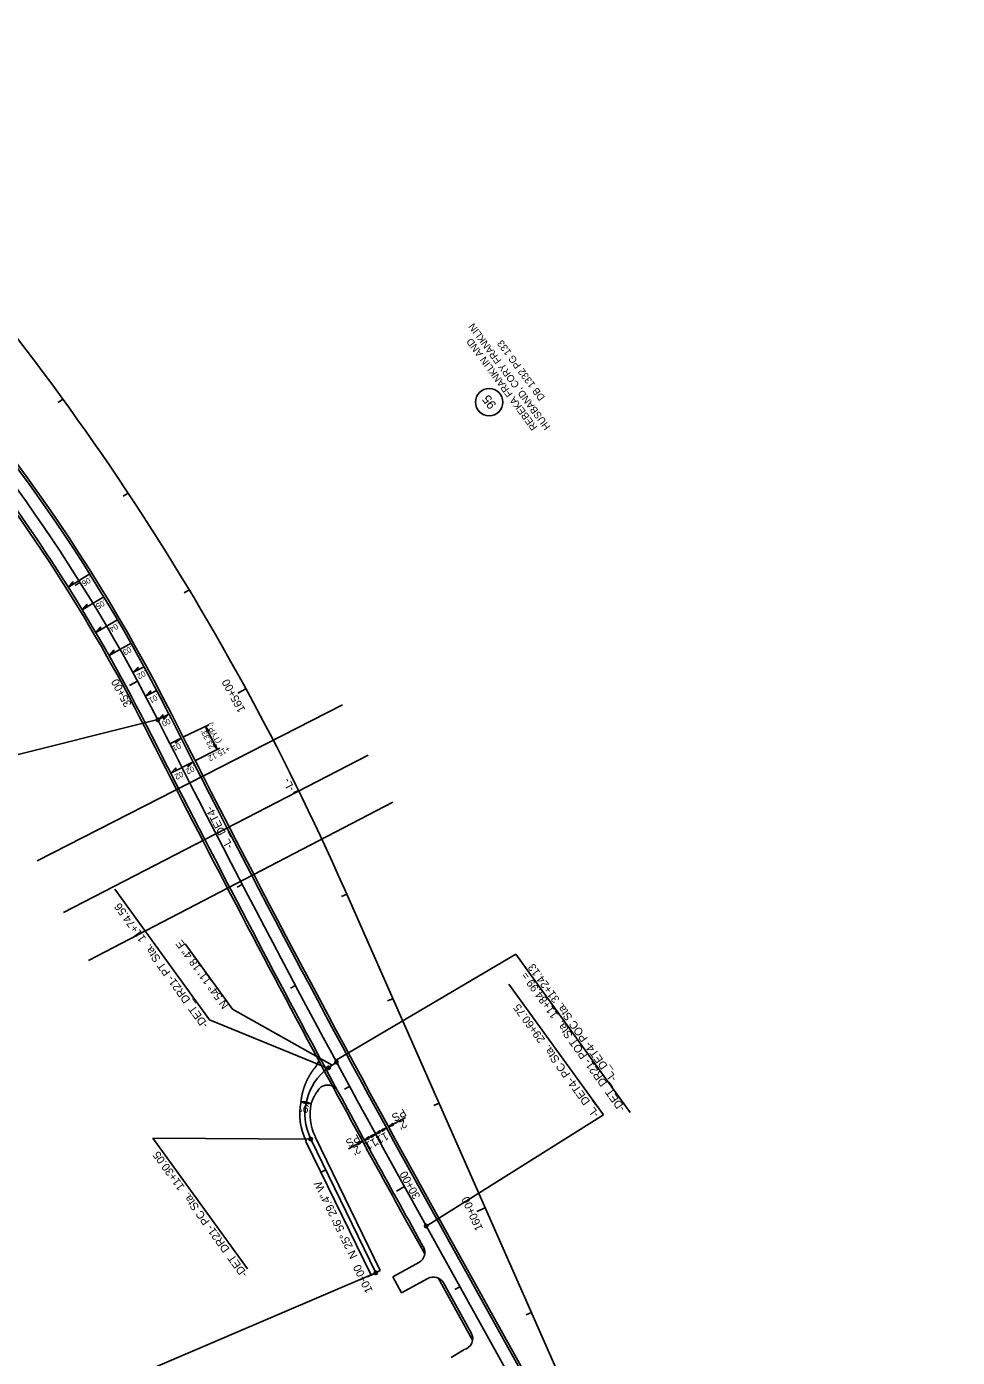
# Model space of a CAD drawing. Extents: x 473658 to 481584, y 489119 to 506230.
# Drawn here: x 475478 to 476292, y 501786 to 502950 of the extents above; entities that cross this region are included whole.
import ezdxf

# ---------------------------------------------------------------- set-up
doc = ezdxf.new("R2010")
doc.units = 0
for name, color, linetype in [('Default', 7, 'Continuous'), ('Exist Horizontal Alignment', 7, 'Continuous'), ('Prop Dimension', 7, 'Continuous'), ('Prop EOT', 7, 'Continuous'), ('Prop Horizontal Alignment', 7, 'Continuous'), ('Prop Horizontal Alignment Direction Label', 7, 'Continuous'), ('Prop Horizontal Alignment Station Label', 7, 'Continuous'), ('Prop Horizontal Alignment Tick Label', 7, 'Continuous'), ('Prop Horizontal Alignment Tick Large', 7, 'Continuous'), ('Prop Horizontal Alignment Tick Small', 7, 'Continuous'), ('Prop Paved Shoulder', 7, 'Continuous'), ('Prop Superelevation  Arrow CELL', 7, 'Continuous'), ('Prop Superelevation Label', 7, 'Continuous'), ('Scratch_Level_1', 7, 'Continuous'), ('Scratch_Level_6', 7, 'Continuous'), ('Sheet Profile Grid Major CELL', 7, 'Continuous')]:
    doc.layers.add(name, color=color, linetype=linetype)

msp = doc.modelspace()

# ---------------------------------------------------------------- linework, layer by layer
at = {"layer": 'Default'}
msp.add_line((475882.6, 502621.3), (475882.6, 502621.3), dxfattribs=at)
msp.add_circle((475882.6, 502621.3), 12, dxfattribs=at)
at = {"layer": 'Exist Horizontal Alignment'}
for points in [[(475788.5, 501985), (475792.8, 501986.5), (475789.3, 501983.6), (475789.4, 501984.6)], [(475798.9, 501988.9), (475794.6, 501987.4), (475798.2, 501990.3), (475798.1, 501989.3)], [(475767.5, 501973.5), (475771.8, 501974.9), (475768.2, 501972.1), (475768.3, 501973.1)], [(475777.9, 501977.4), (475773.5, 501975.9), (475777.1, 501978.8), (475777, 501977.8)], [(475778.9, 501979.7), (475783.2, 501981.2), (475779.6, 501978.3), (475779.7, 501979.3)], [(475787.5, 501982.7), (475783.2, 501981.2), (475786.8, 501984.1), (475786.7, 501983.1)]]:
    msp.add_lwpolyline(points, close=True, dxfattribs=at)
at = {"layer": 'Prop Dimension'}
for p, q in [((475792.8, 501986.5), (475773.5, 501975.9)), ((475809.5, 501995.6), (475794.6, 501987.4)), ((475771.8, 501974.9), (475759.5, 501968.2))]:
    msp.add_line(p, q, dxfattribs=at)
at = {"layer": 'Prop EOT'}
for p, q in [((476290.2, 501090.7), (475837.1, 501906.2)), ((475825, 501882.5), (475817.9, 501895.5)), ((475798.2, 501856.2), (475821.2, 501868.9)), ((475798.2, 501856.2), (475806, 501842.2)), ((475806, 501842.2), (475828.9, 501855)), ((475866.9, 501807.2), (475842.5, 501851.1)), ((475849.4, 501785.9), (475860.5, 501792.6))]:
    msp.add_line(p, q, dxfattribs=at)
for centre, radius, start, end in [((474253.9, 501667.1), 1511, 26.8016, 47.101), ((474253.9, 501667.1), 1489, 26.8016, 38.8133), ((486928.5, 508069.9), 12689, 206.80164, 209.06204), ((486928.5, 508069.9), 12711, 206.80164, 208.25921), ((486928.5, 508069.9), 12711, 208.25921, 209.06204), ((475816.3, 501877.7), 10, 299.0603, 29.062), ((475833.8, 501846.2), 10, 29.062, 119.0603), ((475858.2, 501802.4), 10, 283.4582, 29.062)]:
    msp.add_arc(centre, radius, start, end, dxfattribs=at)
at = {"layer": 'Prop Horizontal Alignment'}
for p, q in [((475999.2, 501644.7), (475755.7, 502196.2)), ((476280.6, 501085.4), (475827.5, 501900.8))]:
    msp.add_line(p, q, dxfattribs=at)
for centre, radius, start, end in [((474253.9, 501667.1), 1500, 26.8016, 58.7771), ((473624.1, 501255.4), 2330, 23.8164, 43.3736), ((486928.5, 508069.9), 12700, 206.80164, 209.06204)]:
    msp.add_arc(centre, radius, start, end, dxfattribs=at)
at = {"layer": 'Prop Horizontal Alignment Station Label'}
for p, q in [((475594.1, 502344.1), (475451.5, 502308.3)), ((475899.9, 502112.3), (475982.6, 501998.1)), ((475828.8, 501901.5), (475982.6, 501998.1))]:
    msp.add_line(p, q, dxfattribs=at)
for centre in [(475592.8, 502343.5), (475827.5, 501900.8)]:
    msp.add_circle(centre, 1.5, dxfattribs=at)
at = {"layer": 'Prop Horizontal Alignment Tick Large'}
for p, q in [((475575.1, 502377.3), (475568.1, 502373.6)), ((475669.9, 502370.6), (475662.9, 502366.7)), ((475808.5, 501935.2), (475801.5, 501931.3)), ((475879.1, 501916.6), (475871.8, 501913.4))]:
    msp.add_line(p, q, dxfattribs=at)
at = {"layer": 'Prop Horizontal Alignment Tick Small'}
for p, q in [((475509.8, 502624), (475505.7, 502621.1)), ((475566.8, 502541.8), (475562.6, 502539.1)), ((475524.9, 502463.8), (475520.6, 502461.1)), ((475620.2, 502457.3), (475615.9, 502454.7)), ((475620.8, 502288.4), (475616.3, 502286.1)), ((475715.9, 502281.8), (475711.4, 502279.6)), ((475666.7, 502199.5), (475662.2, 502197.2)), ((475758, 502191.1), (475753.4, 502189.1)), ((475713.2, 502111), (475708.8, 502108.7)), ((475798.4, 502099.6), (475793.8, 502097.6)), ((475760.5, 502022.9), (475756.1, 502020.5)), ((475838.8, 502008.1), (475834.2, 502006.1)), ((475857, 501847.7), (475852.6, 501845.3)), ((475919.5, 501825.1), (475914.9, 501823.1))]:
    msp.add_line(p, q, dxfattribs=at)
at = {"layer": 'Prop Paved Shoulder'}
for p, q in [((476292, 501091.7), (475838.8, 501907.1)), ((475826.2, 501876.3), (475816.1, 501894.5)), ((475868.1, 501801), (475837.9, 501855.3))]:
    msp.add_line(p, q, dxfattribs=at)
for centre, radius, start, end in [((474253.9, 501667.1), 1513, 26.8016, 46.3329), ((474253.9, 501667.1), 1487, 26.8016, 39.0451), ((486928.5, 508069.9), 12687, 206.80164, 209.06204), ((486928.5, 508069.9), 12713, 206.80164, 208.28624), ((486928.5, 508069.9), 12713, 208.28624, 209.06204)]:
    msp.add_arc(centre, radius, start, end, dxfattribs=at)
at = {"layer": 'Prop Superelevation  Arrow CELL'}
for points in [[(475514.6, 502459.4), (475518.6, 502464.3), (475518.5, 502461.8)], [(475526.8, 502439.7), (475530.8, 502444.5), (475530.7, 502442.1)], [(475538.6, 502419.8), (475542.8, 502424.6), (475542.6, 502422.1)], [(475550.2, 502399.7), (475554.4, 502404.4), (475554.2, 502402)], [(475571.1, 502384.8), (475575.4, 502389.4), (475575.2, 502387)], [(475582.2, 502364.2), (475586.5, 502368.8), (475586.3, 502366.4)], [(475592.8, 502343.5), (475597.2, 502348), (475596.9, 502345.6)], [(475602.6, 502348.4), (475598.2, 502343.9), (475598.5, 502346.3)], [(475636, 502333.2), (475634.7, 502337.5), (475637.5, 502333.9), (475636.5, 502334)], [(475613.1, 502327.6), (475608.7, 502323.1), (475609, 502325.5)], [(475643.4, 502322), (475644.7, 502317.6), (475642, 502321.3), (475643, 502321.1)], [(475604.1, 502296.8), (475608.5, 502301.4), (475608.2, 502298.9)], [(475623.7, 502306.8), (475619.3, 502302.3), (475619.6, 502304.7)]]:
    msp.add_lwpolyline(points, close=True, dxfattribs=at)
at = {"layer": 'Prop Superelevation Label'}
for p, q in [((475514.6, 502459.4), (475533.3, 502471.1)), ((475526.8, 502439.7), (475545.6, 502451.1)), ((475538.7, 502419.8), (475557.6, 502430.9)), ((475550.2, 502399.8), (475569.4, 502410.6)), ((475571.1, 502384.8), (475580.8, 502390)), ((475582.1, 502364.2), (475591.9, 502369.3)), ((475592.8, 502343.5), (475602.6, 502348.4)), ((475637.3, 502339), (475615.3, 502328.7)), ((475644.7, 502317.5), (475634.5, 502337.7)), ((475603.3, 502322.6), (475613.2, 502327.6)), ((475625.9, 502308), (475647.1, 502318.7)), ((475604.1, 502296.8), (475623.7, 502306.8))]:
    msp.add_line(p, q, dxfattribs=at)
at = {"layer": 'Scratch_Level_1'}
for p, q in [((475638, 502081.1), (475555.3, 502195.4)), ((475658, 502090.4), (475616.6, 502147.5)), ((475748.2, 502045.4), (475905.8, 502138.6)), ((476006, 502000.1), (475905.8, 502138.6)), ((475740.7, 502039), (475638, 502081.1)), ((475658, 502090.4), (475745.3, 502041.5)), ((475742.2, 502039.2), (475749, 502044.1)), ((475726.9, 502007.7), (475718, 502009.5)), ((475671.3, 501863.3), (475588.5, 501977.6)), ((475588.5, 501977.6), (475726.5, 501976.8)), ((475779.3, 501857.9), (475722.4, 501974.8)), ((475783.4, 501859.8), (475726.5, 501976.8)), ((475787.4, 501861.8), (475730.5, 501978.8)), ((475739.6, 501949.8), (475735.1, 501947.6)), ((475782, 501859.2), (475564.5, 501766.2)), ((475783.4, 501859.8), (475776.2, 501856.3)), ((475787.4, 501861.8), (475779.3, 501857.9))]:
    msp.add_line(p, q, dxfattribs=at)
for points in [[(475722.3, 502007.9), (475718, 502009.5), (475722.6, 502009.4), (475721.9, 502008.7)], [(475722.6, 502009.4), (475726.9, 502007.7), (475722.3, 502007.8), (475723, 502008.5)]]:
    msp.add_lwpolyline(points, close=True, dxfattribs=at)
for centre in [(475749, 502044.1), (475742.2, 502039.2), (475726.5, 501976.8), (475783.4, 501859.8)]:
    msp.add_circle(centre, 1.5, dxfattribs=at)
for centre, radius, start, end in [((475723.6, 502047), 10, 321.1552, 28.2592), ((475771.5, 501998.7), 50, 125.8116, 205.9415), ((475741.4, 502014.1), 10, 28.4274, 146.4124), ((475771.5, 501998.7), 54.5, 168.5148, 205.9415), ((475771.5, 501998.7), 45.5, 168.5148, 205.9415)]:
    msp.add_arc(centre, radius, start, end, dxfattribs=at)
for points in [[(475731.4, 502040.7), (475730.2, 502039.3), (475730.2, 502039.2), (475730.2, 502039.2), (475730.1, 502039.1), (475730, 502038.9), (475729.9, 502038.8), (475729.8, 502038.7), (475729.7, 502038.6), (475729.6, 502038.5), (475729.5, 502038.3), (475729.4, 502038.2), (475729.3, 502038.1), (475729.2, 502038), (475729.1, 502037.8), (475729, 502037.7), (475728.9, 502037.6), (475728.8, 502037.5), (475728.7, 502037.3), (475728.6, 502037.2), (475728.5, 502037.1), (475728.5, 502036.9), (475728.4, 502036.8), (475728.3, 502036.7), (475728.2, 502036.6), (475728.1, 502036.4), (475728, 502036.3), (475727.9, 502036.2), (475727.8, 502036.1), (475727.7, 502035.9), (475727.6, 502035.8), (475727.6, 502035.7), (475727.5, 502035.5), (475727.4, 502035.4), (475727.3, 502035.3), (475727.2, 502035.2), (475727.1, 502035), (475727, 502034.9), (475726.9, 502034.8), (475726.9, 502034.6), (475726.8, 502034.5), (475726.7, 502034.4), (475726.6, 502034.2), (475726.5, 502034.1), (475726.4, 502034), (475726.4, 502033.8), (475726.3, 502033.7), (475726.2, 502033.6), (475726.1, 502033.4), (475726, 502033.3), (475726, 502033.2), (475725.9, 502033.1), (475725.8, 502032.9), (475725.7, 502032.8), (475725.6, 502032.7), (475725.6, 502032.5), (475725.5, 502032.4), (475725.4, 502032.3), (475725.3, 502032.1), (475725.2, 502032), (475725.2, 502031.9), (475725.1, 502031.7), (475725, 502031.6), (475724.9, 502031.4), (475724.9, 502031.3), (475724.8, 502031.2), (475724.7, 502031), (475724.6, 502030.9), (475724.6, 502030.8), (475724.5, 502030.6), (475724.4, 502030.5), (475724.3, 502030.4), (475724.3, 502030.2), (475724.2, 502030.1), (475724.1, 502030), (475724.1, 502029.8), (475724, 502029.7), (475723.9, 502029.5), (475723.8, 502029.4), (475723.8, 502029.3), (475723.7, 502029.1), (475723.6, 502029), (475723.6, 502028.9), (475723.5, 502028.7), (475723.4, 502028.6), (475723.4, 502028.4), (475723.3, 502028.3), (475723.2, 502028.2), (475723.2, 502028), (475723.1, 502027.9), (475723, 502027.7), (475723, 502027.6), (475722.9, 502027.5), (475722.8, 502027.3), (475722.8, 502027.2), (475722.7, 502027.1), (475722.6, 502026.9), (475722.6, 502026.8), (475722.5, 502026.6), (475722.5, 502026.5), (475722.4, 502026.4), (475722.3, 502026.2), (475722.3, 502026.1), (475722.2, 502025.9), (475722.2, 502025.8), (475722.1, 502025.6), (475722, 502025.5), (475722, 502025.4), (475721.9, 502025.2), (475721.9, 502025.1), (475721.8, 502024.9), (475721.8, 502024.8), (475721.7, 502024.7), (475721.6, 502024.5), (475721.6, 502024.4), (475721.5, 502024.2), (475721.5, 502024.1), (475721.4, 502023.9), (475721.4, 502023.8), (475721.3, 502023.7), (475721.3, 502023.5), (475721.2, 502023.4), (475721.2, 502023.2), (475721.1, 502023.1), (475721.1, 502023), (475721, 502022.8), (475720.9, 502022.7), (475720.9, 502022.5), (475720.8, 502022.4), (475720.8, 502022.2), (475720.7, 502022.1), (475720.7, 502021.9), (475720.7, 502021.8), (475720.6, 502021.7), (475720.6, 502021.5), (475720.5, 502021.4), (475720.5, 502021.2), (475720.4, 502021.1), (475720.4, 502020.9), (475720.3, 502020.8), (475720.3, 502020.6), (475720.2, 502020.5), (475720.2, 502020.4), (475720.1, 502020.2), (475720.1, 502020.1), (475720.1, 502019.9), (475720, 502019.8), (475720, 502019.6), (475719.9, 502019.5), (475719.9, 502019.3), (475719.9, 502019.2), (475719.8, 502019.1), (475719.8, 502018.9), (475719.7, 502018.8), (475719.7, 502018.6), (475719.7, 502018.5), (475719.6, 502018.3), (475719.6, 502018.2), (475719.5, 502018), (475719.5, 502017.9), (475719.5, 502017.7), (475719.4, 502017.6), (475719.4, 502017.5), (475719.4, 502017.3), (475719.3, 502017.2), (475719.3, 502017), (475719.2, 502016.9), (475719.2, 502016.7), (475719.2, 502016.6), (475719.1, 502016.4), (475719.1, 502016.3), (475719.1, 502016.1), (475719.1, 502016), (475719, 502015.8), (475719, 502015.7), (475719, 502015.5), (475718.9, 502015.4), (475718.9, 502015.3), (475718.9, 502015.1), (475718.8, 502015), (475718.8, 502014.8), (475718.8, 502014.7), (475718.8, 502014.5), (475718.7, 502014.4), (475718.7, 502014.2), (475718.7, 502014.1), (475718.6, 502013.9), (475718.6, 502013.8), (475718.6, 502013.6), (475718.6, 502013.5), (475718.5, 502013.3), (475718.5, 502013.2), (475718.5, 502013), (475718.5, 502012.9), (475718.4, 502012.8), (475718.4, 502012.6), (475718.4, 502012.5), (475718.4, 502012.3), (475718.4, 502012.2), (475718.3, 502012), (475718.3, 502011.9), (475718.3, 502011.7), (475718.3, 502011.6), (475718.3, 502011.4), (475718.2, 502011.3), (475718.2, 502011.1), (475718.2, 502011), (475718.2, 502010.8), (475718.2, 502010.7), (475718.2, 502010.5), (475718.1, 502010.4), (475718.1, 502010.1), (475718.1, 502009.8), (475718, 502009.5)], [(475733, 502019.7), (475731.9, 502017.9), (475731.9, 502017.9), (475731.8, 502017.9), (475731.8, 502017.8), (475731.7, 502017.7), (475731.6, 502017.6), (475731.6, 502017.5), (475731.5, 502017.4), (475731.4, 502017.3), (475731.4, 502017.2), (475731.3, 502017.1), (475731.3, 502017), (475731.2, 502016.9), (475731.1, 502016.8), (475731.1, 502016.7), (475731, 502016.6), (475730.9, 502016.5), (475730.9, 502016.4), (475730.8, 502016.3), (475730.8, 502016.2), (475730.7, 502016), (475730.6, 502015.9), (475730.6, 502015.8), (475730.5, 502015.7), (475730.4, 502015.6), (475730.4, 502015.5), (475730.3, 502015.4), (475730.3, 502015.3), (475730.2, 502015.2), (475730.1, 502015.1), (475730.1, 502015), (475730, 502014.9), (475730, 502014.8), (475729.9, 502014.7), (475729.9, 502014.6), (475729.8, 502014.5), (475729.7, 502014.4), (475729.7, 502014.2), (475729.6, 502014.1), (475729.6, 502014), (475729.5, 502013.9), (475729.5, 502013.8), (475729.4, 502013.7), (475729.3, 502013.6), (475729.3, 502013.5), (475729.2, 502013.4), (475729.2, 502013.3), (475729.1, 502013.2), (475729.1, 502013.1), (475729, 502012.9), (475729, 502012.8), (475728.9, 502012.7), (475728.9, 502012.6), (475728.8, 502012.5), (475728.8, 502012.4), (475728.7, 502012.3), (475728.7, 502012.2), (475728.6, 502012.1), (475728.5, 502012), (475728.5, 502011.8), (475728.4, 502011.7), (475728.4, 502011.6), (475728.3, 502011.5), (475728.3, 502011.4), (475728.2, 502011.3), (475728.2, 502011.2), (475728.1, 502011.1), (475728.1, 502010.9), (475728.1, 502010.8), (475728, 502010.7), (475728, 502010.6), (475727.9, 502010.5), (475727.9, 502010.4), (475727.8, 502010.3), (475727.8, 502010.1), (475727.7, 502010), (475727.7, 502009.9), (475727.6, 502009.8), (475727.6, 502009.7), (475727.5, 502009.6), (475727.5, 502009.5), (475727.5, 502009.3), (475727.4, 502009.2), (475727.4, 502009.1), (475727.3, 502009), (475727.3, 502008.9), (475727.2, 502008.8), (475727.2, 502008.7), (475727.2, 502008.5), (475727.1, 502008.4), (475727, 502008.2), (475726.9, 502008), (475726.9, 502007.7)]]:
    msp.add_open_spline(points, degree=3, dxfattribs=at)
at = {"layer": 'Scratch_Level_6'}
for p, q in [((475487.2, 502220.1), (475754.3, 502356.7)), ((475510.3, 502175.1), (475776.9, 502312.7)), ((475532.2, 502132.9), (475798.3, 502271.5))]:
    msp.add_line(p, q, dxfattribs=at)

# ---------------------------------------------------------------- texts
at = {"layer": 'Default'}
for s, height, p in [('HUSBAND, CORY FRANKLIN', 6.25, (475936.4, 502599.9)), ('REBEKA FRANKLIN AND', 6.25, (475925.1, 502599.5)), ('DB 1332 PG 133', 6.25, (475931.6, 502625.5)), ('95', 8, (475889.3, 502619))]:
    msp.add_text(s, height=height, rotation=126.4463, dxfattribs=at).set_placement(p)
at = {"layer": 'Prop Horizontal Alignment Direction Label'}
msp.add_text('-L_DET4-', height=7, rotation=117.1564, dxfattribs=at).set_placement((475658.8, 502232.7))
at = {"layer": 'Prop Horizontal Alignment Station Label'}
for s, rotation, p in [('-L-', 116.4493, (475712.9, 502283.1)), ('-L_DET4- PC Sta.  29+60.75', 125.9074, (475979.1, 501998.7))]:
    msp.add_text(s, height=7, rotation=rotation, dxfattribs=at).set_placement(p)
at = {"layer": 'Prop Horizontal Alignment Tick Label'}
for s, rotation, p in [('35+00', 118.2616, (475570.2, 502357)), ('165+00', 118.5954, (475669.6, 502352.3)), ('30+00', 118.8849, (475822.7, 501926.6)), ('160+00', 113.8164, (475877.3, 501898.5))]:
    msp.add_text(s, height=7, rotation=rotation, dxfattribs=at).set_placement(p)
at = {"layer": 'Prop Superelevation Label'}
for s, rotation, p in [('.06', 212.2546, (475533.7, 502469.2)), ('.05', 211.3635, (475545.9, 502449.1)), ('.04', 210.4723, (475557.9, 502428.9)), ('.03', 209.5812, (475569.6, 502408.6)), ('.02', 208.6892, (475582.1, 502387.5)), ('.01', 207.798, (475592.5, 502366.4)), ('.00', 207.0121, (475604, 502345.9)), ('(TYP.)', 116.9158, (475648.4, 502324.4)), ('.01', 207.0121, (475613.1, 502324.4)), ("23.33'", 116.9158, (475642.7, 502319.5)), ('+15.12', 207.1397, (475654.5, 502320.9)), ('.02', 207.0121, (475624.9, 502304.2)), ('.02', 207.0121, (475615.2, 502299.5))]:
    msp.add_text(s, height=5, rotation=rotation, dxfattribs=at).set_placement(p)
at = {"layer": 'Scratch_Level_1'}
for s, rotation, p in [('-DET_DR21- PT Sta.  11+74.56', 125.9074, (475637.5, 502076.8)), ('N 54%%d 11\' 18.4" E', 125.8116, (475655.3, 502093.9)), ('-L_DET4- POC Sta. 31+24.13', 125.8116, (475994.5, 502029.9)), ('-DET_DR21- POT Sta.  11+84.99 = ', 125.8116, (476002, 502004)), ("9'", 168.5148, (475725.5, 502006.2)), ('-DET_DR21- PC Sta.  11+30.05', 125.9074, (475671.8, 501858.8)), ('N 25%%d 56\' 29.4" W', 115.9415, (475767.7, 501874.3)), ('10+00', 115.9415, (475781, 501844.2))]:
    msp.add_text(s, height=7, rotation=rotation, dxfattribs=at).set_placement(p)
at = {"layer": 'Sheet Profile Grid Major CELL'}
for s, p in [('PS', (475807.6, 502003.8)), ("2'", (475808.2, 501994.1)), ('PS', (475767.4, 501981.5)), ("11'", (475782.4, 501977.9)), ("11'", (475792.2, 501983.2)), ("2'", (475767.9, 501971.7))]:
    msp.add_text(s, height=7, rotation=208.6481, dxfattribs=at).set_placement(p)

doc.saveas('drawing.dxf')
